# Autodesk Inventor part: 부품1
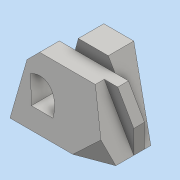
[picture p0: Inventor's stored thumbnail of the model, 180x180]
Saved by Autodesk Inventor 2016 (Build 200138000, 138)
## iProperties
Created: 2023-02
Part Number: 부품1
Material: 일반
Document SubType Name: Modeling
Designer: PC-1-11
Density: 1 g/cm^3
Appearance: 기본값
Author: PC-1-11
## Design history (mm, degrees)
sketch "스케치1"
  geometry: L1 (0, 0)-(-105, 0); L2 (-105, 0)-(-105, 57); L3 (-105, 57)-(0, 57); L4 (0, 57)-(0, 0)
  constraints: 8 end point, 2 parallel, 1 horizontal, 1 perpendicular
  dimensions: "d0" = 105 distance between parallel lines of L2 L4; "d1" = 57 distance between parallel lines of L3 L1
extrude "돌출1" new body sketch "스케치1" distance "d2" = 45; taper "d3" = 0 deg
sketch "스케치3"
  geometry: L1 (105, 0)-(72.091, 57); L2 (105, 57)-(0, 57) reference; L3 (0, 57)-(105, 57) reference; L4 (72.091, 57)-(105, 57); L5 (105, 57)-(105, 0); L6 (0, 0)-(105, 0) reference
  constraints: 6 end point, 1 collinear, 1 perpendicular, 1 point on line
  dimensions: "d9" = 60 deg angle of L1 L6
extrude "돌출2" cut sketch "스케치3" distance "d10" = 33; taper "d11" = 0 deg
sketch "스케치4"
  geometry: L1 (105, 0)-(105, 33) reference; L2 (105, 0)-(72.091, 0) reference; L3 (105, 0)-(105, 13); L4 (105, 13)-(70, 0); L5 (0, 0)-(105, 0) reference; L6 (70, 0)-(105, 0)
  constraints: 6 end point, 2 point on line, 1 collinear
  dimensions: "d12" = 13 distance from line of L2 L3.end; "d13" = 35 distance from line of L1 L4.end
extrude "돌출3" cut sketch "스케치4" stored distance "d14" = 33; taper "d15" = 0 deg
sketch "스케치5"
  geometry: L1 (17, 17)-(41, 17); L2 (17, 17)-(7.238, 38.925); L3 (0, 0)-(70, 0) reference; L4 (0, 57)-(0, 0) reference; A1 r 24 centre (17, 17) between (0, 0.059) and (0.059, 0); A2 r 24 centre (17, 17) between (41, 17) and (7.238, 38.925)
  constraints: 4 end point, 4 point on circle, 2 centre point, 2 point on line, 1 horizontal
  dimensions: "d16" = 17 distance between parallel lines of L1 L3; "d17" = 17 distance from line of L1.start L4; "d18" = 114 deg angle of L1 L2; "d19" = 24 distance of L1.end L1.start
extrude "돌출4" cut sketch "스케치5" stored distance "d20" = 33; taper "d21" = 0 deg
chamfer "모따기1" distance "d22" = 10; stored, may be unused: second distance "d23" = 2, angle "d24" = 45 deg
sketch "스케치6"
  geometry: L1 (57, -45)-(0, -21.971); L2 (0, -21.971)-(0, -45); L3 (0, -45)-(57, -45); L4 (57, -45)-(57, 0) reference; L5 (0, -44.223)-(0, -12) reference
  constraints: 6 end point, 1 collinear, 1 horizontal, 1 vertical
  dimensions: "d25" = 68 deg angle of L4 L1
extrude "돌출5" cut sketch "스케치6" stored distance "d26" = 33; taper "d27" = 0 deg
sketch "스케치7"
  geometry: L1 (105, 0)-(72.091, 57) reference; L2 (105, 26)-(87.102, 57); L3 (72.091, 57)-(105, 57) reference; L4 (105, 57)-(87.102, 57); L5 (105, 57)-(105, 26); L6 (105, 57)-(105, 0) reference
  constraints: 6 end point, 2 point on line, 1 parallel
  dimensions: "d28" = 13 distance between parallel lines of L1 L2
extrude "돌출6" cut sketch "스케치7" distance "d29" = 33; taper "d30" = 0 deg
sketch "스케치2"
  geometry: L1 (105, 0)-(0, 0) reference; L2 (105, 0)-(64.585, -70); L3 (64.585, -70)-(31.201, -70); L4 (0, 0)-(0, -57) reference; L5 (0, 0)-(105, 0); L6 (17, -17)-(41, -17) reference; L7 (7.238, -38.925)-(17, -17) reference; L8 (17, -17)-(41, -17) reference; L9 (17, -17)-(31.201, -70); L10 (17, -17)-(17, 0)
  constraints: 10 end point, 1 collinear, 1 parallel, 1 perpendicular, 1 point on line
  dimensions: "d4" = 60 deg angle of L1 L2; "d5" = 70 distance between parallel lines of L1 L3; "d31" = 75 deg angle of L9 L6
extrude "돌출7" join sketch "스케치2" distance "d32" = 40; taper "d33" = 0 deg
sketch "스케치8"
  geometry: L1 (105, 0)-(17, 0) reference; L2 (17, 0)-(41, 0); L3 (41, 0)-(41, -17); L4 (41, -17)-(17, -17); L5 (17, -17)-(17, 0); 1 further point
  constraints: 8 end point, 2 parallel, 1 horizontal, 1 perpendicular
  dimensions: "d34" = 17 distance between parallel lines of L4 L1; "d35" = 24 distance between parallel lines of L5 L3
extrude "돌출8" cut sketch "스케치8" stored distance "d36" = 40; taper "d37" = 0 deg
sketch "스케치9"
  geometry: L1 (26, 19)-(-44, 40.401); L2 (-44, 40.401)-(-44, 59); L3 (-44, 12)-(-44, 52) reference; L4 (-44, 59)-(26, 59); L5 (26, 59)-(26, 19); L6 (26, 12)-(26, 52) reference; 1 further point
  constraints: 8 end point, 2 collinear, 1 horizontal, 1 perpendicular, 1 point on line
  dimensions: "d38" = 52 distance of L1.start point (26, -33); "d39" = 73 deg angle of L5 L1; "d40" = 40 distance from line of L1.start L4
extrude "돌출9" cut sketch "스케치9" stored distance "d41" = 40; taper "d42" = 0 deg
node "솔리드1"
